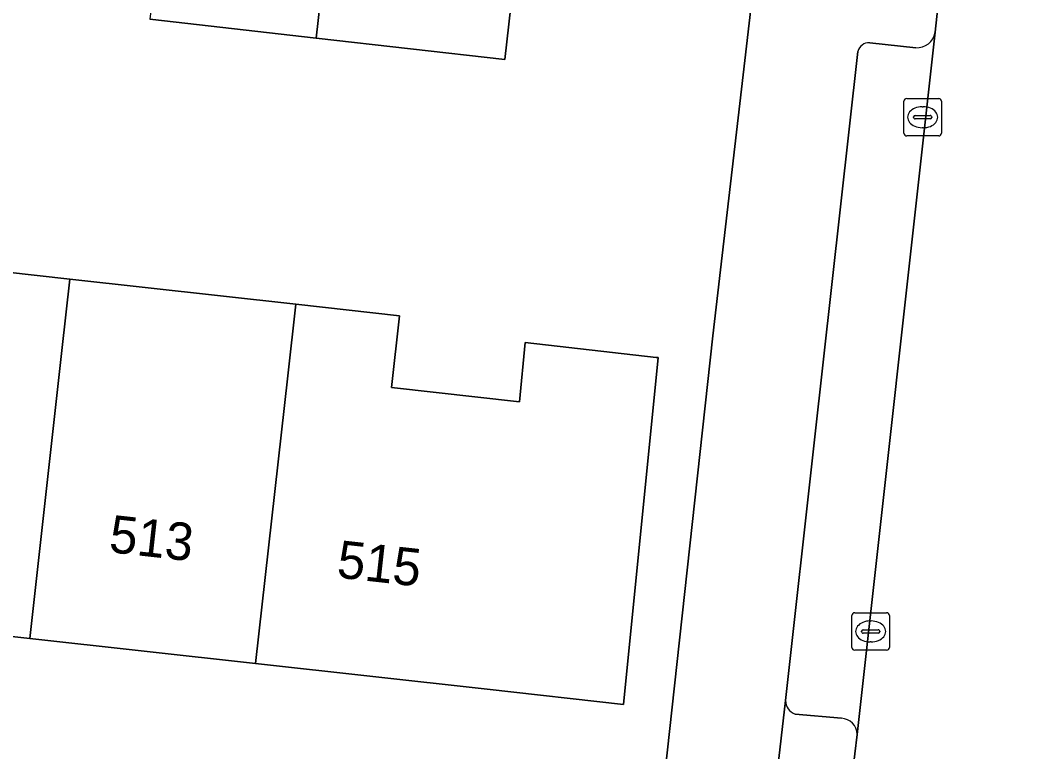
# Model space of a CAD drawing. Extents: x 161928 to 163071, y 386474 to 387428.
# Drawn here: x 162091.72 to 162118.72, y 387168.84 to 387188.36 of the extents above; entities that cross this region are included whole.
import ezdxf

# ---------------------------------------------------------------- set-up
doc = ezdxf.new("R2010")
doc.units = 0
for name, color, linetype in [('IMGEO_Erf', 7, 'Continuous'), ('IMGEO_Kolk', 7, 'Continuous'), ('IMGEO_Muur', 7, 'Continuous'), ('IMGEO_Pand', 7, 'Continuous'), ('IMGEO_Pand_nummerreeks', 7, 'Continuous'), ('IMGEO_Parkeervlak_open', 7, 'Continuous'), ('IMGEO_Rijbaan_lokaal_open', 7, 'Continuous'), ('IMGEO_Voetpad_open', 7, 'Continuous')]:
    doc.layers.add(name, color=color, linetype=linetype)

msp = doc.modelspace()

# ---------------------------------------------------------------- linework, layer by layer
at = {"layer": 'IMGEO_Erf'}
for points in [[(162104.967, 387190.151), (162104.642, 387187.308), (162099.609, 387187.884), (162095.175, 387188.391)], [(162067.599, 387169.823), (162106.527, 387165.525), (162106.712, 387165.513), (162106.897, 387165.517), (162107.081, 387165.538), (162107.263, 387165.575), (162107.44, 387165.629), (162107.612, 387165.698), (162107.777, 387165.782), (162107.934, 387165.88), (162108.081, 387165.992), (162108.218, 387166.117), (162108.343, 387166.254), (162108.456, 387166.401), (162108.555, 387166.557), (162108.639, 387166.722), (162108.709, 387166.894), (162108.763, 387167.071), (162108.8, 387167.253), (162108.814, 387167.351), (162109.099, 387169.955), (162110.193, 387179.937), (162111.295, 387189.434)], [(162087.018, 387182.126), (162093.04, 387181.455), (162099.065, 387180.784), (162101.835, 387180.475), (162101.622, 387178.561), (162105.031, 387178.18), (162105.189, 387179.759), (162108.683, 387179.366), (162108.728, 387179.361), (162107.807, 387170.107), (162104.174, 387170.511), (162097.997, 387171.198), (162091.972, 387171.869), (162085.946, 387172.54)]]:
    msp.add_lwpolyline(points, dxfattribs=at)
at = {"layer": 'IMGEO_Kolk'}
for p, q in [((162115.286, 387185.346), (162115.286, 387186.198)), ((162115.361, 387186.272), (162116.213, 387186.272)), ((162116.287, 387186.198), (162116.287, 387185.346)), ((162115.588, 387185.815), (162115.986, 387185.815)), ((162115.774, 387186.052), (162115.799, 387186.052)), ((162115.545, 387185.766), (162115.545, 387185.778)), ((162115.983, 387185.729), (162115.585, 387185.729)), ((162116.029, 387185.778), (162116.029, 387185.766)), ((162115.797, 387185.492), (162115.772, 387185.492)), ((162116.213, 387185.272), (162115.361, 387185.272)), ((162113.899, 387171.628), (162113.899, 387172.48)), ((162113.974, 387172.554), (162114.826, 387172.554)), ((162114.387, 387172.334), (162114.412, 387172.334)), ((162114.9, 387172.48), (162114.9, 387171.628)), ((162114.158, 387172.048), (162114.158, 387172.06)), ((162114.201, 387172.097), (162114.599, 387172.097)), ((162114.642, 387172.06), (162114.642, 387172.048)), ((162114.596, 387172.011), (162114.198, 387172.011)), ((162114.41, 387171.774), (162114.385, 387171.774)), ((162114.826, 387171.554), (162113.974, 387171.554))]:
    msp.add_line(p, q, dxfattribs=at)
for points in [[(162115.286, 387185.346), (162115.286, 387186.198)], [(162115.361, 387186.272), (162116.213, 387186.272)], [(162116.287, 387186.198), (162116.287, 387185.346)], [(162116.213, 387185.272), (162115.361, 387185.272)], [(162113.899, 387171.628), (162113.899, 387172.48)], [(162113.974, 387172.554), (162114.826, 387172.554)], [(162114.9, 387172.48), (162114.9, 387171.628)], [(162114.826, 387171.554), (162113.974, 387171.554)]]:
    msp.add_lwpolyline(points, dxfattribs=at)
for centre, radius, start, end in [((162115.363, 387186.196), 0.0765, 91.552, 178.448), ((162115.363, 387186.196), 0.0765, 91.552, 178.448), ((162116.211, 387186.196), 0.0765, 1.552, 88.448), ((162116.211, 387186.196), 0.0765, 1.552, 88.448), ((162115.585, 387185.775), 0.0403, 85.8775, 175.7526), ((162115.99, 387185.777), 0.0386, 1.7309, 96.639), ((162115.582, 387185.765), 0.0366, 178.938, 274.7102), ((162115.986, 387185.772), 0.043, 264.8664, 352.4533), ((162115.363, 387185.348), 0.0765, 181.552, 268.448), ((162115.363, 387185.348), 0.0765, 181.552, 268.448), ((162116.211, 387185.348), 0.0765, 271.552, 358.448), ((162116.211, 387185.348), 0.0765, 271.552, 358.448), ((162113.976, 387172.478), 0.0765, 91.552, 178.448), ((162113.976, 387172.478), 0.0765, 91.552, 178.448), ((162114.824, 387172.478), 0.0765, 1.552, 88.448), ((162114.824, 387172.478), 0.0765, 1.552, 88.448), ((162114.198, 387172.057), 0.0403, 85.8775, 175.7526), ((162114.195, 387172.047), 0.0366, 178.938, 274.7102), ((162114.599, 387172.054), 0.043, 264.8664, 352.4533), ((162114.603, 387172.059), 0.0386, 1.7309, 96.639), ((162113.976, 387171.63), 0.0765, 181.552, 268.448), ((162113.976, 387171.63), 0.0765, 181.552, 268.448), ((162114.824, 387171.63), 0.0765, 271.552, 358.448), ((162114.824, 387171.63), 0.0765, 271.552, 358.448)]:
    msp.add_arc(centre, radius, start, end, dxfattribs=at)
for centre, major_axis, ratio, start_param, end_param in [((162115.773, 387185.772), (-0.387, 0.002), 0.722429, 4.712389, 7.853982), ((162115.798, 387185.772), (-0.39, 0.002), 0.717154, 1.570796, 4.712389), ((162114.386, 387172.054), (-0.387, 0.002), 0.722429, 4.712389, 7.853982), ((162114.411, 387172.054), (-0.39, 0.002), 0.717154, 1.570796, 4.712389)]:
    msp.add_ellipse(centre, major_axis=major_axis, ratio=ratio, start_param=start_param, end_param=end_param, dxfattribs=at)
at = {"layer": 'IMGEO_Muur'}
msp.add_lwpolyline([(162109.166, 387189.675), (162111.295, 387189.434), (162110.193, 387179.937)], dxfattribs=at)
at = {"layer": 'IMGEO_Pand'}
for points in [[(162095.5, 387191.234), (162095.175, 387188.391), (162099.609, 387187.884), (162099.771, 387189.306), (162100.368, 387189.238), (162100.53, 387190.659)], [(162100.53, 387190.659), (162100.368, 387189.238), (162099.771, 387189.306), (162099.609, 387187.884), (162104.642, 387187.308), (162104.967, 387190.151)], [(162093.04, 387181.455), (162087.018, 387182.126), (162086.801, 387180.219), (162085.946, 387172.54), (162091.972, 387171.869), (162092.827, 387179.545)], [(162092.827, 387179.545), (162091.972, 387171.869), (162097.997, 387171.198), (162098.852, 387178.871), (162099.065, 387180.784), (162093.04, 387181.455)], [(162105.031, 387178.18), (162101.622, 387178.561), (162101.835, 387180.475), (162099.065, 387180.784), (162098.852, 387178.871), (162097.997, 387171.198), (162104.174, 387170.511), (162107.807, 387170.107), (162108.728, 387179.361), (162108.683, 387179.366), (162105.189, 387179.759)]]:
    msp.add_lwpolyline(points, close=True, dxfattribs=at)
at = {"layer": 'IMGEO_Parkeervlak_open'}
for points in [[(162114.042, 387169.308), (162116.121, 387188.038)], [(162115.6, 387187.627), (162114.374, 387187.755)], [(162114.06, 387187.522), (162112.905, 387177.165), (162112.13, 387170.209)], [(162112.387, 387169.85), (162113.619, 387169.74)]]:
    msp.add_lwpolyline(points, dxfattribs=at)
for centre, radius, start, end in [((162115.635, 387188.118), 0.492, 265.8975, 350.64), ((162114.346, 387187.464), 0.292, 84.5906, 168.5631), ((162112.513, 387170.212), 0.383, 180.4389, 250.7572), ((162113.59, 387169.289), 0.452, 2.4361, 86.3578)]:
    msp.add_arc(centre, radius, start, end, dxfattribs=at)
at = {"layer": 'IMGEO_Rijbaan_lokaal_open'}
msp.add_lwpolyline([(162126.448, 387235.259), (162128.563, 387254.234), (162130.777, 387274.349), (162125.812, 387274.929), (162125.677, 387273.645), (162125.041, 387267.693), (162124.036, 387258.734), (162123.853, 387257.116), (162123.558, 387254.485), (162117.072, 387196.521), (162116.857, 387194.692), (162116.195, 387188.705), (162116.121, 387188.038), (162114.042, 387169.308), (162113.916, 387168.273), (162118.898, 387167.619), (162118.995, 387168.628), (162119.765, 387175.585)], close=True, dxfattribs=at)
at = {"layer": 'IMGEO_Voetpad_open'}
for points in [[(162114.072, 387233.552), (162113.903, 387232.017), (162109.887, 387195.59), (162109.7, 387194.065), (162109.367, 387191.043), (162109.166, 387189.675), (162111.295, 387189.434), (162110.193, 387179.937), (162109.099, 387169.955), (162108.814, 387167.351), (162108.8, 387167.253), (162108.763, 387167.071), (162108.709, 387166.894), (162108.639, 387166.722), (162108.555, 387166.557), (162108.456, 387166.401), (162108.343, 387166.254), (162108.218, 387166.117), (162108.081, 387165.992), (162107.934, 387165.88), (162107.727, 387163.616)], [(162116.121, 387188.038), (162116.195, 387188.705), (162115.17, 387188.837), (162115.85, 387194.803), (162116.857, 387194.692), (162117.072, 387196.521)], [(162114.374, 387187.755), (162115.6, 387187.627)], [(162104.803, 387105.513), (162109.419, 387146.635), (162112.13, 387170.209), (162112.905, 387177.165), (162114.06, 387187.522)], [(162112.13, 387170.209), (162109.419, 387146.635)], [(162113.619, 387169.74), (162112.387, 387169.85)], [(162113.916, 387168.273), (162114.042, 387169.308)]]:
    msp.add_lwpolyline(points, dxfattribs=at)
for centre, radius, start, end in [((162115.635, 387188.118), 0.492, 265.8975, 350.64), ((162114.346, 387187.464), 0.292, 84.5906, 168.5631), ((162112.513, 387170.212), 0.383, 180.4389, 250.7572), ((162113.59, 387169.289), 0.452, 2.4361, 86.3578)]:
    msp.add_arc(centre, radius, start, end, dxfattribs=at)

# ---------------------------------------------------------------- texts
at = {"layer": 'IMGEO_Pand_nummerreeks'}
for s, rotation, p in [('513', 353.6493, (162094.06, 387174.172)), ('515', 353.6516, (162100.136, 387173.496))]:
    msp.add_text(s, height=1, rotation=rotation, dxfattribs=at).set_placement(p)

doc.saveas('drawing.dxf')
